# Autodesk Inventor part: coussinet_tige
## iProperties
Shininess: 64.0
Length Units: 11269
Angle Units: 11279
Time Units: 11290
Mass Units: 11283
Length Display Precision: 3
Angle Display Precision: 2
Compacted: True
Part Number: coussinet_tige
Document SubType Name: Modeling
Created: 2004-05
Material: Par défaut
Designer: David
Density: 0.0
Volumn: 0.0
Area: 0.0
PropertySet Name: Model Information
Control State: 0
Master: False
Checked Out: False
Author: David
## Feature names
1. Révolution1 [Revolution]
